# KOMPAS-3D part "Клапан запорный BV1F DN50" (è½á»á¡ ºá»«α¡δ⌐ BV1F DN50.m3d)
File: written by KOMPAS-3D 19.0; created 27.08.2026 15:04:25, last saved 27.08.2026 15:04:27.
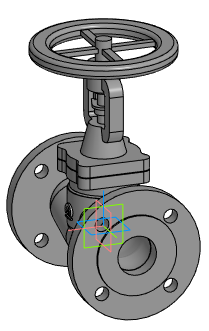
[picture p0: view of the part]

Document properties: Автор: Энергия; Полное имя файла: E:\Dendor\_3D для проектировщиков\5.6 Клапан запорный BV1F\stp\Клапан запорный BV1F DN50.m3d

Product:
- Part/product: Клапан запорный BV1F DN50
    Масса: 15.4579

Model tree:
1. Операция без истории:1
